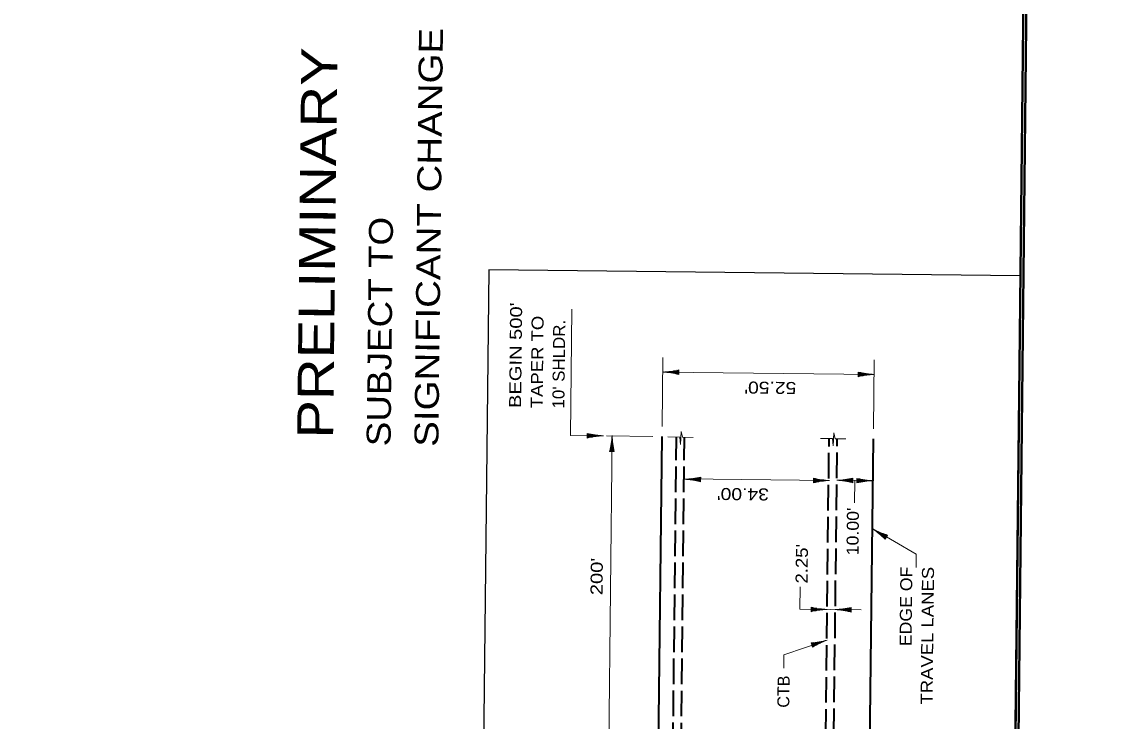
# Model space of a CAD drawing. Extents: x 2356576 to 2377878, y 6966390 to 6990634.
# Drawn here: x 2365341 to 2367164, y 6975215 to 6976378 of the extents above; entities that cross this region are included whole.
import ezdxf
from ezdxf.enums import TextEntityAlignment as Align

# ---------------------------------------------------------------- set-up
doc = ezdxf.new("R2010")
doc.units = 0
doc.header["$LTSCALE"] = 7.1
doc.linetypes.add('LONG_DASHED', pattern=[7.5, 6, -1.5])
doc.layers.add('19', color=7, linetype='Continuous', lineweight=13)
doc.layers.add('8', color=7, linetype='Continuous', lineweight=13)
doc.layers.add('5', color=7, linetype='Continuous')

msp = doc.modelspace()

# ---------------------------------------------------------------- linework, layer by layer
at = {"layer": '19'}
for p, q in [((2366406.7, 6975819.54), (2366405.426, 6975704.906)), ((2366758.252, 6975815.63), (2366756.978, 6975700.998)), ((2366406.432, 6975795.416), (2366757.982, 6975791.51)), ((2366433.052, 6975795.224), (2366407.928, 6975795.528)), ((2366433.042, 6975794.226), (2366415.824, 6975794.436)), ((2366433.064, 6975796.224), (2366418.37, 6975796.402)), ((2366433.028, 6975793.224), (2366423.308, 6975793.342)), ((2366433.08, 6975797.224), (2366424.528, 6975797.33)), ((2366433.088, 6975798.224), (2366429.92, 6975798.264)), ((2366433.098, 6975798.926), (2366433.004, 6975791.266)), ((2366731.356, 6975793.38), (2366741.082, 6975793.38)), ((2366731.36, 6975787.678), (2366731.358, 6975795.34)), ((2366731.358, 6975794.38), (2366736.118, 6975794.38)), ((2366433.02, 6975792.224), (2366428.258, 6975792.282)), ((2366731.356, 6975791.382), (2366756.484, 6975791.382)), ((2366731.356, 6975789.38), (2366739.91, 6975789.378)), ((2366731.36, 6975792.38), (2366748.576, 6975792.378)), ((2366731.36, 6975788.38), (2366734.528, 6975788.38)), ((2366731.362, 6975790.38), (2366746.056, 6975790.38)), ((2366281.046, 6975692.304), (2366285.81, 6975692.304)), ((2366281.048, 6975685.602), (2366281.05, 6975693.264)), ((2366281.048, 6975691.304), (2366290.77, 6975691.304)), ((2366281.048, 6975690.304), (2366298.268, 6975690.302)), ((2366281.048, 6975689.306), (2366306.176, 6975689.306)), ((2366281.048, 6975687.304), (2366289.602, 6975687.302)), ((2366281.048, 6975686.304), (2366284.216, 6975686.304)), ((2366281.05, 6975688.304), (2366295.748, 6975688.304)), ((2366313, 6975689.19), (2366389.762, 6975688.338)), ((2366316.114, 6975117.774), (2366322.458, 6975689.086)), ((2366322.098, 6975663.168), (2366322.4, 6975688.292)), ((2366319.096, 6975663.202), (2366319.154, 6975667.964)), ((2366320.098, 6975663.192), (2366320.216, 6975672.914)), ((2366321.1, 6975663.18), (2366321.31, 6975680.398)), ((2366323.098, 6975663.158), (2366323.274, 6975677.852)), ((2366324.098, 6975663.142), (2366324.202, 6975671.694)), ((2366325.098, 6975663.132), (2366325.136, 6975666.3)), ((2366325.8, 6975663.124), (2366318.138, 6975663.216)), ((2366441.958, 6975617.528), (2366682.336, 6975614.858)), ((2366469.478, 6975616.924), (2366444.354, 6975617.228)), ((2366469.464, 6975615.926), (2366452.248, 6975616.136)), ((2366469.486, 6975617.924), (2366454.794, 6975618.102)), ((2366469.454, 6975614.924), (2366459.732, 6975615.042)), ((2366469.504, 6975618.924), (2366460.95, 6975619.03)), ((2366469.442, 6975613.924), (2366464.68, 6975613.982)), ((2366469.512, 6975619.924), (2366466.344, 6975619.964)), ((2366469.52, 6975620.626), (2366469.43, 6975612.966)), ((2366657.206, 6975617.856), (2366661.97, 6975617.856)), ((2366657.208, 6975611.154), (2366657.21, 6975618.816)), ((2366657.208, 6975616.856), (2366666.93, 6975616.856)), ((2366657.208, 6975615.856), (2366674.428, 6975615.854)), ((2366657.208, 6975614.858), (2366682.336, 6975614.858)), ((2366657.208, 6975612.856), (2366665.762, 6975612.854)), ((2366657.208, 6975611.856), (2366660.376, 6975611.856)), ((2366657.21, 6975613.856), (2366671.908, 6975613.856)), ((2366695.844, 6975615.434), (2366755.84, 6975614.768)), ((2366722.468, 6975615.24), (2366697.344, 6975615.544)), ((2366722.454, 6975614.242), (2366705.236, 6975614.452)), ((2366722.478, 6975616.24), (2366707.782, 6975616.418)), ((2366722.444, 6975613.24), (2366712.72, 6975613.358)), ((2366722.492, 6975617.24), (2366713.94, 6975617.346)), ((2366722.432, 6975612.24), (2366717.67, 6975612.298)), ((2366722.504, 6975618.24), (2366719.336, 6975618.28)), ((2366722.512, 6975618.942), (2366722.42, 6975611.282)), ((2366725.4, 6975578.082), (2366725.81, 6975615.1)), ((2366729.216, 6975617.638), (2366733.98, 6975617.638)), ((2366729.218, 6975610.936), (2366729.22, 6975618.598)), ((2366729.218, 6975616.638), (2366738.94, 6975616.638)), ((2366729.218, 6975615.638), (2366746.438, 6975615.636)), ((2366729.218, 6975614.64), (2366754.346, 6975614.64)), ((2366729.218, 6975612.638), (2366737.772, 6975612.636)), ((2366729.218, 6975611.638), (2366732.386, 6975611.638)), ((2366729.22, 6975613.638), (2366743.918, 6975613.638)), ((2366778.55, 6975520.87), (2366756.97, 6975533.744)), ((2366778.038, 6975520.014), (2366763.248, 6975528.834)), ((2366779.058, 6975521.73), (2366766.438, 6975529.26)), ((2366777.524, 6975519.154), (2366769.174, 6975524.134)), ((2366779.572, 6975522.588), (2366772.228, 6975526.97)), ((2366777.012, 6975518.294), (2366772.924, 6975520.734)), ((2366780.444, 6975524.05), (2366776.52, 6975517.47)), ((2366780.084, 6975523.448), (2366777.366, 6975525.072)), ((2366634.652, 6975401.042), (2366635.062, 6975437.896)), ((2366634.652, 6975401.042), (2366736.69, 6975399.908)), ((2366652.994, 6975402.412), (2366662.718, 6975402.412)), ((2366652.996, 6975396.71), (2366652.998, 6975404.372)), ((2366652.996, 6975403.412), (2366657.758, 6975403.412)), ((2366652.996, 6975400.414), (2366678.124, 6975400.414)), ((2366652.996, 6975398.412), (2366661.548, 6975398.41)), ((2366652.996, 6975397.412), (2366656.164, 6975397.412)), ((2366652.998, 6975401.412), (2366670.214, 6975401.41)), ((2366652.998, 6975399.412), (2366667.696, 6975399.412)), ((2366719.742, 6975400.2), (2366694.618, 6975400.504)), ((2366719.728, 6975399.202), (2366702.512, 6975399.412)), ((2366719.75, 6975401.2), (2366705.058, 6975401.378)), ((2366719.718, 6975398.2), (2366709.994, 6975398.318)), ((2366719.768, 6975402.2), (2366711.214, 6975402.306)), ((2366719.706, 6975397.2), (2366714.944, 6975397.258)), ((2366719.776, 6975403.2), (2366716.61, 6975403.24)), ((2366719.784, 6975403.902), (2366719.694, 6975396.242)), ((2366679.656, 6975349.472), (2366608.084, 6975325.316)), ((2366655.496, 6975337.652), (2366653.144, 6975344.944)), ((2366653.436, 6975344.03), (2366657.966, 6975345.492)), ((2366653.744, 6975343.078), (2366662.996, 6975346.064)), ((2366654.05, 6975342.126), (2366670.438, 6975347.412)), ((2366654.356, 6975341.176), (2366678.272, 6975348.89)), ((2366654.668, 6975340.224), (2366668.652, 6975344.736)), ((2366654.972, 6975339.272), (2366663.11, 6975341.896)), ((2366655.278, 6975338.32), (2366658.296, 6975339.292)), ((2366608.084, 6975325.316), (2366607.834, 6975302.84))]:
    msp.add_line(p, q, dxfattribs=at)
at = {"layer": '19', "lineweight": 35}
for p, q in [((2366392.98, 6974584.292), (2366405.238, 6975688.026)), ((2366737.734, 6973980.518), (2366756.652, 6975684.12))]:
    msp.add_line(p, q, dxfattribs=at)
at = {"layer": '19', "linetype": 'LONG_DASHED', "lineweight": 35}
for p, q in [((2366416.98, 6974584.026), (2366429.232, 6975687.326)), ((2366430.48, 6974583.876), (2366442.728, 6975686.9)), ((2366670.546, 6974553.35), (2366683.116, 6975684.936)), ((2366684.054, 6974554.04), (2366696.614, 6975684.786))]:
    msp.add_line(p, q, dxfattribs=at)
at = {"layer": '19', "lineweight": 40}
msp.add_lwpolyline([(2363758.773, 6990629.355), (2367158.576, 6990592.767), (2366922.891, 6968646.236), (2363523.088, 6968682.826)], close=True, dxfattribs=at)
at = {"layer": '19', "lineweight": 25}
msp.add_lwpolyline([(2366974.866, 6973617.03), (2367000.838, 6975955.59), (2366117.376, 6975965.402), (2366091.406, 6973626.842)], close=True, dxfattribs=at)
at = {"layer": '19'}
for points in [[(2366255.436, 6975900.148), (2366253.102, 6975690.016), (2366307.032, 6975689.416)], [(2366414.868, 6975687.486), (2366434.692, 6975687.266), (2366436.206, 6975674.864), (2366437.274, 6975696.592), (2366439.094, 6975686.94), (2366456.99, 6975686.742)], [(2366668.752, 6975685.096), (2366688.576, 6975684.876), (2366690.09, 6975672.474), (2366691.158, 6975694.202), (2366692.978, 6975684.55), (2366710.874, 6975684.352)], [(2366755.616, 6975534.398), (2366827.858, 6975492.61), (2366827.608, 6975470.134)]]:
    msp.add_lwpolyline(points, dxfattribs=at)
for centre, start, end in [((2366401.013, 6975939.74), 272.14997, 282.83602), ((2366397.521, 6975651.267), 75.77681, 86.46286), ((2366765.141, 6975935.759), 256.47239, 267.15844), ((2366765.151, 6975647.265), 92.84556, 103.53161), ((2366314.83, 6975833.682), 256.47239, 267.15844), ((2366314.84, 6975545.188), 92.84556, 103.53161), ((2366178.138, 6975698.703), 345.77681, 356.46286), ((2366466.611, 6975695.211), 182.14997, 192.83602), ((2366437.437, 6975761.44), 272.14997, 282.83602), ((2366433.945, 6975472.967), 75.77681, 86.46286), ((2366690.991, 6975759.234), 256.47239, 267.15844), ((2366691.001, 6975470.74), 92.84556, 103.53161), ((2366690.427, 6975759.756), 272.14997, 282.83602), ((2366686.935, 6975471.283), 75.77681, 86.46286), ((2366763.001, 6975759.016), 256.47239, 267.15844), ((2366763.011, 6975470.522), 92.84556, 103.53161), ((2366675.571, 6975414.185), 45.65522, 56.34127), ((2366823.358, 6975661.951), 242.02838, 252.71443), ((2366686.779, 6975544.79), 256.47239, 267.15844), ((2366686.789, 6975256.296), 92.84556, 103.53161), ((2366687.701, 6975544.716), 272.14997, 282.83602), ((2366684.209, 6975256.243), 75.77681, 86.46286), ((2366642.184, 6975488.952), 274.35136, 285.03741), ((2366730.763, 6975214.393), 110.72452, 121.41057)]:
    msp.add_arc(centre, 144.425, start, end, dxfattribs=at)
at = {"layer": '8'}
for p, q in [((2366406.7, 6975819.54), (2366405.426, 6975704.906)), ((2366758.252, 6975815.63), (2366756.978, 6975700.998)), ((2366406.432, 6975795.416), (2366757.982, 6975791.51)), ((2366433.052, 6975795.224), (2366407.928, 6975795.528)), ((2366433.042, 6975794.226), (2366415.824, 6975794.436)), ((2366433.064, 6975796.224), (2366418.37, 6975796.402)), ((2366433.028, 6975793.224), (2366423.308, 6975793.342)), ((2366433.08, 6975797.224), (2366424.528, 6975797.33)), ((2366433.088, 6975798.224), (2366429.92, 6975798.264)), ((2366433.098, 6975798.926), (2366433.004, 6975791.266)), ((2366731.356, 6975793.38), (2366741.082, 6975793.38)), ((2366731.36, 6975787.678), (2366731.358, 6975795.34)), ((2366731.358, 6975794.38), (2366736.118, 6975794.38)), ((2366433.02, 6975792.224), (2366428.258, 6975792.282)), ((2366731.356, 6975791.382), (2366756.484, 6975791.382)), ((2366731.356, 6975789.38), (2366739.91, 6975789.378)), ((2366731.36, 6975792.38), (2366748.576, 6975792.378)), ((2366731.36, 6975788.38), (2366734.528, 6975788.38)), ((2366731.362, 6975790.38), (2366746.056, 6975790.38)), ((2366281.046, 6975692.304), (2366285.81, 6975692.304)), ((2366281.048, 6975685.602), (2366281.05, 6975693.264)), ((2366281.048, 6975691.304), (2366290.77, 6975691.304)), ((2366281.048, 6975690.304), (2366298.268, 6975690.302)), ((2366281.048, 6975689.306), (2366306.176, 6975689.306)), ((2366281.048, 6975687.304), (2366289.602, 6975687.302)), ((2366281.048, 6975686.304), (2366284.216, 6975686.304)), ((2366281.05, 6975688.304), (2366295.748, 6975688.304)), ((2366313, 6975689.19), (2366389.762, 6975688.338)), ((2366316.114, 6975117.774), (2366322.458, 6975689.086)), ((2366322.098, 6975663.168), (2366322.4, 6975688.292)), ((2366319.096, 6975663.202), (2366319.154, 6975667.964)), ((2366320.098, 6975663.192), (2366320.216, 6975672.914)), ((2366321.1, 6975663.18), (2366321.31, 6975680.398)), ((2366323.098, 6975663.158), (2366323.274, 6975677.852)), ((2366324.098, 6975663.142), (2366324.202, 6975671.694)), ((2366325.098, 6975663.132), (2366325.136, 6975666.3)), ((2366325.8, 6975663.124), (2366318.138, 6975663.216)), ((2366441.958, 6975617.528), (2366682.336, 6975614.858)), ((2366469.478, 6975616.924), (2366444.354, 6975617.228)), ((2366469.464, 6975615.926), (2366452.248, 6975616.136)), ((2366469.486, 6975617.924), (2366454.794, 6975618.102)), ((2366469.454, 6975614.924), (2366459.732, 6975615.042)), ((2366469.504, 6975618.924), (2366460.95, 6975619.03)), ((2366469.442, 6975613.924), (2366464.68, 6975613.982)), ((2366469.512, 6975619.924), (2366466.344, 6975619.964)), ((2366469.52, 6975620.626), (2366469.43, 6975612.966)), ((2366657.206, 6975617.856), (2366661.97, 6975617.856)), ((2366657.208, 6975611.154), (2366657.21, 6975618.816)), ((2366657.208, 6975616.856), (2366666.93, 6975616.856)), ((2366657.208, 6975615.856), (2366674.428, 6975615.854)), ((2366657.208, 6975614.858), (2366682.336, 6975614.858)), ((2366657.208, 6975612.856), (2366665.762, 6975612.854)), ((2366657.208, 6975611.856), (2366660.376, 6975611.856)), ((2366657.21, 6975613.856), (2366671.908, 6975613.856)), ((2366695.844, 6975615.434), (2366755.84, 6975614.768)), ((2366722.468, 6975615.24), (2366697.344, 6975615.544)), ((2366722.454, 6975614.242), (2366705.236, 6975614.452)), ((2366722.478, 6975616.24), (2366707.782, 6975616.418)), ((2366722.444, 6975613.24), (2366712.72, 6975613.358)), ((2366722.492, 6975617.24), (2366713.94, 6975617.346)), ((2366722.432, 6975612.24), (2366717.67, 6975612.298)), ((2366722.504, 6975618.24), (2366719.336, 6975618.28)), ((2366722.512, 6975618.942), (2366722.42, 6975611.282)), ((2366725.4, 6975578.082), (2366725.81, 6975615.1)), ((2366729.216, 6975617.638), (2366733.98, 6975617.638)), ((2366729.218, 6975610.936), (2366729.22, 6975618.598)), ((2366729.218, 6975616.638), (2366738.94, 6975616.638)), ((2366729.218, 6975615.638), (2366746.438, 6975615.636)), ((2366729.218, 6975614.64), (2366754.346, 6975614.64)), ((2366729.218, 6975612.638), (2366737.772, 6975612.636)), ((2366729.218, 6975611.638), (2366732.386, 6975611.638)), ((2366729.22, 6975613.638), (2366743.918, 6975613.638)), ((2366778.55, 6975520.87), (2366756.97, 6975533.744)), ((2366778.038, 6975520.014), (2366763.248, 6975528.834)), ((2366779.058, 6975521.73), (2366766.438, 6975529.26)), ((2366777.524, 6975519.154), (2366769.174, 6975524.134)), ((2366779.572, 6975522.588), (2366772.228, 6975526.97)), ((2366777.012, 6975518.294), (2366772.924, 6975520.734)), ((2366780.444, 6975524.05), (2366776.52, 6975517.47)), ((2366780.084, 6975523.448), (2366777.366, 6975525.072)), ((2366634.652, 6975401.042), (2366635.062, 6975437.896)), ((2366634.652, 6975401.042), (2366736.69, 6975399.908)), ((2366652.994, 6975402.412), (2366662.718, 6975402.412)), ((2366652.996, 6975396.71), (2366652.998, 6975404.372)), ((2366652.996, 6975403.412), (2366657.758, 6975403.412)), ((2366652.996, 6975400.414), (2366678.124, 6975400.414)), ((2366652.996, 6975398.412), (2366661.548, 6975398.41)), ((2366652.996, 6975397.412), (2366656.164, 6975397.412)), ((2366652.998, 6975401.412), (2366670.214, 6975401.41)), ((2366652.998, 6975399.412), (2366667.696, 6975399.412)), ((2366719.742, 6975400.2), (2366694.618, 6975400.504)), ((2366719.728, 6975399.202), (2366702.512, 6975399.412)), ((2366719.75, 6975401.2), (2366705.058, 6975401.378)), ((2366719.718, 6975398.2), (2366709.994, 6975398.318)), ((2366719.768, 6975402.2), (2366711.214, 6975402.306)), ((2366719.706, 6975397.2), (2366714.944, 6975397.258)), ((2366719.776, 6975403.2), (2366716.61, 6975403.24)), ((2366719.784, 6975403.902), (2366719.694, 6975396.242)), ((2366679.656, 6975349.472), (2366608.084, 6975325.316)), ((2366655.496, 6975337.652), (2366653.144, 6975344.944)), ((2366653.436, 6975344.03), (2366657.966, 6975345.492)), ((2366653.744, 6975343.078), (2366662.996, 6975346.064)), ((2366654.05, 6975342.126), (2366670.438, 6975347.412)), ((2366654.356, 6975341.176), (2366678.272, 6975348.89)), ((2366654.668, 6975340.224), (2366668.652, 6975344.736)), ((2366654.972, 6975339.272), (2366663.11, 6975341.896)), ((2366655.278, 6975338.32), (2366658.296, 6975339.292)), ((2366608.084, 6975325.316), (2366607.834, 6975302.84))]:
    msp.add_line(p, q, dxfattribs=at)
at = {"layer": '8', "lineweight": 35}
for p, q in [((2366392.98, 6974584.292), (2366405.238, 6975688.026)), ((2366737.734, 6973980.518), (2366756.652, 6975684.12))]:
    msp.add_line(p, q, dxfattribs=at)
at = {"layer": '8', "linetype": 'LONG_DASHED', "lineweight": 35}
for p, q in [((2366416.98, 6974584.026), (2366429.232, 6975687.326)), ((2366430.48, 6974583.876), (2366442.728, 6975686.9)), ((2366670.546, 6974553.35), (2366683.116, 6975684.936)), ((2366684.054, 6974554.04), (2366696.614, 6975684.786))]:
    msp.add_line(p, q, dxfattribs=at)
at = {"layer": '8', "lineweight": 40}
for points in [[(2363753.827, 6990634.409), (2367163.63, 6990597.713), (2366927.837, 6968641.182), (2363518.034, 6968677.88)], [(2363758.773, 6990629.355), (2367158.576, 6990592.767), (2366922.891, 6968646.236), (2363523.088, 6968682.826)]]:
    msp.add_lwpolyline(points, close=True, dxfattribs=at)
at = {"layer": '8', "lineweight": 25}
msp.add_lwpolyline([(2366974.866, 6973617.03), (2367000.838, 6975955.59), (2366117.376, 6975965.402), (2366091.406, 6973626.842)], close=True, dxfattribs=at)
at = {"layer": '8'}
for points in [[(2366255.436, 6975900.148), (2366253.102, 6975690.016), (2366307.032, 6975689.416)], [(2366414.868, 6975687.486), (2366434.692, 6975687.266), (2366436.206, 6975674.864), (2366437.274, 6975696.592), (2366439.094, 6975686.94), (2366456.99, 6975686.742)], [(2366668.752, 6975685.096), (2366688.576, 6975684.876), (2366690.09, 6975672.474), (2366691.158, 6975694.202), (2366692.978, 6975684.55), (2366710.874, 6975684.352)], [(2366755.616, 6975534.398), (2366827.858, 6975492.61), (2366827.608, 6975470.134)]]:
    msp.add_lwpolyline(points, dxfattribs=at)
for centre, start, end in [((2366401.013, 6975939.74), 272.14997, 282.83602), ((2366397.521, 6975651.267), 75.77681, 86.46286), ((2366765.141, 6975935.759), 256.47239, 267.15844), ((2366765.151, 6975647.265), 92.84556, 103.53161), ((2366314.83, 6975833.682), 256.47239, 267.15844), ((2366314.84, 6975545.188), 92.84556, 103.53161), ((2366178.138, 6975698.703), 345.77681, 356.46286), ((2366466.611, 6975695.211), 182.14997, 192.83602), ((2366437.437, 6975761.44), 272.14997, 282.83602), ((2366433.945, 6975472.967), 75.77681, 86.46286), ((2366690.991, 6975759.234), 256.47239, 267.15844), ((2366691.001, 6975470.74), 92.84556, 103.53161), ((2366690.427, 6975759.756), 272.14997, 282.83602), ((2366686.935, 6975471.283), 75.77681, 86.46286), ((2366763.001, 6975759.016), 256.47239, 267.15844), ((2366763.011, 6975470.522), 92.84556, 103.53161), ((2366675.571, 6975414.185), 45.65522, 56.34127), ((2366823.358, 6975661.951), 242.02838, 252.71443), ((2366686.779, 6975544.79), 256.47239, 267.15844), ((2366686.789, 6975256.296), 92.84556, 103.53161), ((2366687.701, 6975544.716), 272.14997, 282.83602), ((2366684.209, 6975256.243), 75.77681, 86.46286), ((2366642.184, 6975488.952), 274.35136, 285.03741), ((2366730.763, 6975214.393), 110.72452, 121.41057)]:
    msp.add_arc(centre, 144.425, start, end, dxfattribs=at)

# ---------------------------------------------------------------- texts
at = {"layer": '19'}
for s, rotation, width, p in [("BEGIN 500'", 89.364, 1.25, (2366170.796, 6975735.492)), ('TAPER TO', 89.364, 1.15, (2366206.792, 6975735.094)), ("10' SHLDR.", 89.364, 1.05, (2366242.79, 6975734.694)), ("52.50'", 179.364, 1.2, (2366628.716, 6975778.758)), ("34.00'", 179.364, 1.2, (2366583.126, 6975601.768)), ("10.00'", 89.364, 1.1, (2366731.944, 6975490.572)), ("2.25'", 89.364, 1.15, (2366647.256, 6975443.63)), ("200'", 89.364, 1.25, (2366306.242, 6975424.16))]:
    msp.add_text(s, height=20, rotation=rotation, dxfattribs=dict(at, width=width)).set_placement(p)
for s, width, p in [('EDGE OF', 1.1, (2366821.659, 6975471.691)), ('TRAVEL LANES', 1.15, (2366857.658, 6975471.295))]:
    msp.add_text(s, height=20, rotation=89.364, dxfattribs=dict(at, width=width)).set_placement(p, align=Align.RIGHT)
msp.add_text('CTB', height=20, rotation=89.364, dxfattribs=at).set_placement((2366617.508, 6975290.53), align=Align.RIGHT)
at = {"layer": '5'}
for s, height, width, p in [('SIGNIFICANT CHANGE', 39.87, 1.2, (2366033.32, 6975670.916)), ('PRELIMINARY', 59.8, 1.2, (2365858.263, 6975684.462)), ('SUBJECT TO', 39.87, 1.15, (2365953.801, 6975671.799))]:
    msp.add_text(s, height=height, rotation=89.364, dxfattribs=dict(at, width=width)).set_placement(p)
at = {"layer": '8'}
for s, rotation, width, p in [("BEGIN 500'", 89.364, 1.25, (2366170.796, 6975735.492)), ('TAPER TO', 89.364, 1.15, (2366206.792, 6975735.094)), ("10' SHLDR.", 89.364, 1.05, (2366242.79, 6975734.694)), ("52.50'", 179.364, 1.2, (2366628.716, 6975778.758)), ("34.00'", 179.364, 1.2, (2366583.126, 6975601.768)), ("10.00'", 89.364, 1.1, (2366731.944, 6975490.572)), ("2.25'", 89.364, 1.15, (2366647.256, 6975443.63)), ("200'", 89.364, 1.25, (2366306.242, 6975424.16))]:
    msp.add_text(s, height=20, rotation=rotation, dxfattribs=dict(at, width=width)).set_placement(p)
for s, width, p in [('EDGE OF', 1.1, (2366821.659, 6975471.691)), ('TRAVEL LANES', 1.15, (2366857.658, 6975471.295))]:
    msp.add_text(s, height=20, rotation=89.364, dxfattribs=dict(at, width=width)).set_placement(p, align=Align.RIGHT)
msp.add_text('CTB', height=20, rotation=89.364, dxfattribs=at).set_placement((2366617.508, 6975290.53), align=Align.RIGHT)

doc.saveas('drawing.dxf')
